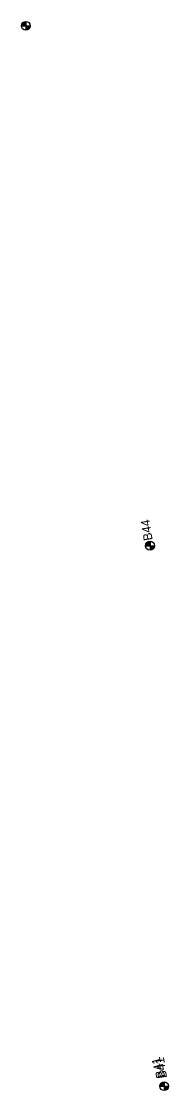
# Model space of a CAD drawing. Extents: x 345549 to 379569, y 127949 to 230467.
# Drawn here: x 360211 to 360377, y 152130 to 153335 of the extents above; entities that cross this region are included whole.
import ezdxf

# ---------------------------------------------------------------- set-up
doc = ezdxf.new("R2010")
doc.units = 0
for name, color, linetype in [('E_SOIL_BORE1 [KAPUR_CADDS_LEVELS]', 7, 'Continuous'), ('E_SOIL_BORE2 [KAPUR_CADDS_LEVELS]', 7, 'Continuous'), ('P_MARK', 7, 'Continuous')]:
    doc.layers.add(name, color=color, linetype=linetype)

msp = doc.modelspace()

# ---------------------------------------------------------------- linework, layer by layer
at = {"layer": 'P_MARK'}
for p, q in [((360211, 153330), (360221, 153330)), ((360216, 153335), (360216, 153325)), ((360356.1, 152749.3), (360356.1, 152739.3)), ((360351.1, 152744.3), (360361.1, 152744.3)), ((360367.1, 152135.4), (360377.1, 152135.4)), ((360372.1, 152140.4), (360372.1, 152130.4))]:
    msp.add_line(p, q, dxfattribs=at)
for centre in [(360216, 153330), (360356.1, 152744.3), (360372.1, 152135.4)]:
    msp.add_circle(centre, 5, dxfattribs=at)
for centre, radius, start, end in [((360216, 153330), 4.5, 89.9869, 179.9869), ((360216, 153330), 4, 89.9869, 179.9869), ((360216, 153330), 3.5, 89.9869, 179.9869), ((360216, 153330), 3, 89.9869, 179.9869), ((360216, 153330), 2.5, 89.9869, 179.9869), ((360216, 153330), 2, 89.9869, 179.9869), ((360216, 153330), 1.5, 89.9869, 179.9869), ((360216, 153330), 1, 89.9869, 179.9869), ((360216, 153330), 0.5, 89.9869, 179.9869), ((360216, 153330), 4.5, 269.9869, 359.9869), ((360216, 153330), 4, 269.9869, 359.9869), ((360216, 153330), 3.5, 269.9869, 359.9869), ((360216, 153330), 3, 269.9869, 359.9869), ((360216, 153330), 2.5, 269.9869, 359.9869), ((360216, 153330), 2, 269.9869, 359.9869), ((360216, 153330), 1.5, 269.9869, 359.9869), ((360216, 153330), 1, 269.9869, 359.9869), ((360216, 153330), 0.5, 269.9869, 359.9869), ((360356.1, 152744.3), 4.5, 89.9869, 179.9869), ((360356.1, 152744.3), 4, 89.9869, 179.9869), ((360356.1, 152744.3), 3.5, 89.9869, 179.9869), ((360356.1, 152744.3), 3, 89.9869, 179.9869), ((360356.1, 152744.3), 2.5, 89.9869, 179.9869), ((360356.1, 152744.3), 2, 89.9869, 179.9869), ((360356.1, 152744.3), 1.5, 89.9869, 179.9869), ((360356.1, 152744.3), 1, 89.9869, 179.9869), ((360356.1, 152744.3), 0.5, 89.9869, 179.9869), ((360356.1, 152744.3), 4.5, 269.9869, 359.9869), ((360356.1, 152744.3), 4, 269.9869, 359.9869), ((360356.1, 152744.3), 3.5, 269.9869, 359.9869), ((360356.1, 152744.3), 3, 269.9869, 359.9869), ((360356.1, 152744.3), 2.5, 269.9869, 359.9869), ((360356.1, 152744.3), 2, 269.9869, 359.9869), ((360356.1, 152744.3), 1.5, 269.9869, 359.9869), ((360356.1, 152744.3), 1, 269.9869, 359.9869), ((360356.1, 152744.3), 0.5, 269.9869, 359.9869), ((360372.1, 152135.4), 4.5, 89.9869, 179.9869), ((360372.1, 152135.4), 4, 89.9869, 179.9869), ((360372.1, 152135.4), 3.5, 89.9869, 179.9869), ((360372.1, 152135.4), 3, 89.9869, 179.9869), ((360372.1, 152135.4), 2.5, 89.9869, 179.9869), ((360372.1, 152135.4), 2, 89.9869, 179.9869), ((360372.1, 152135.4), 1.5, 89.9869, 179.9869), ((360372.1, 152135.4), 1, 89.9869, 179.9869), ((360372.1, 152135.4), 0.5, 89.9869, 179.9869), ((360372.1, 152135.4), 4.5, 269.9869, 359.9869), ((360372.1, 152135.4), 4, 269.9869, 359.9869), ((360372.1, 152135.4), 3.5, 269.9869, 359.9869), ((360372.1, 152135.4), 3, 269.9869, 359.9869), ((360372.1, 152135.4), 2.5, 269.9869, 359.9869), ((360372.1, 152135.4), 2, 269.9869, 359.9869), ((360372.1, 152135.4), 1.5, 269.9869, 359.9869), ((360372.1, 152135.4), 1, 269.9869, 359.9869), ((360372.1, 152135.4), 0.5, 269.9869, 359.9869)]:
    msp.add_arc(centre, radius, start, end, dxfattribs=at)

# ---------------------------------------------------------------- texts
at = {"layer": 'E_SOIL_BORE1 [KAPUR_CADDS_LEVELS]'}
for s, p in [('B44', (360359.1, 152750.8)), ('B41', (360375.4, 152145))]:
    msp.add_text(s, height=10, rotation=98.8576, dxfattribs=at).set_placement(p)
at = {"layer": 'E_SOIL_BORE2 [KAPUR_CADDS_LEVELS]'}
msp.add_text('B41', height=10, rotation=105.7466, dxfattribs=at).set_placement((360373.4, 152146.1))

doc.saveas('drawing.dxf')
